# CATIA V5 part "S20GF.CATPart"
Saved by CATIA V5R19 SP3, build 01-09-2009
Part number: S20GF
Bounding box of the stored display mesh (mm): x -9.827 to 9.827, y -9.827 to 9.827, z -40 to 10
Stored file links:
  C:\Users\d.catalano\Desktop\CATALOGO CAD\S20 GF\S20GF.CATPart
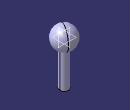
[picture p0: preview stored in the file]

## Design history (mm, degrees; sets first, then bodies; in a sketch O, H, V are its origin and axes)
Body1 (main body)
  Sketch1 on yz-plane, origin (0, 0, 0), H (0, 1, 0), V (0, 0, 1)
    arc A1 centre (0, 0) radius 10 from (0, -10) to (0, 10) ccw
    line L1 (0, -10) -> (0, 10)
    radius A1 = 10
    vertical: L1 V
    coincidence: L1 V
  Shaft1: profile Sketch1, axis Sketch1.L1, angle 360
  Sketch2 on xy-plane, origin (0, 0, 0), H (1, 0, 0), V (0, 1, 0)
    circle A1 centre (0, 0) radius 4
    radius A1 = 4
  Pad1: profile Sketch2, direction (0, 0, -1), length 40
  Thread1: diameter 8, depth 30.8348, pitch 1, on face of Pad1 from Sketch2.A1, from end face of Pad1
